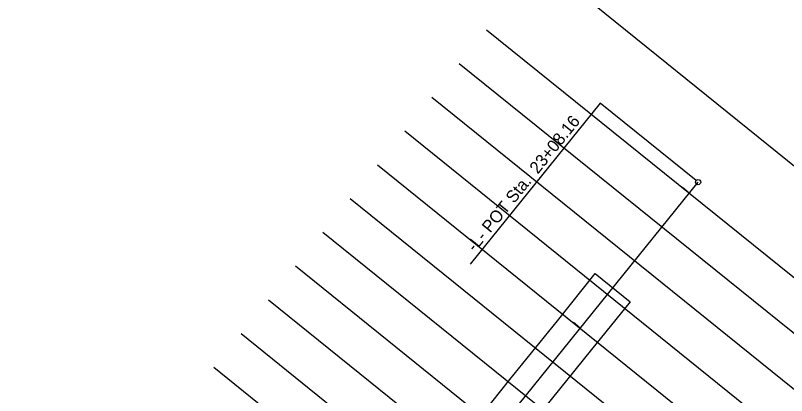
# Model space of a CAD drawing. Extents: x 2292992 to 2295123, y 892701 to 896230.
# Drawn here: x 2293899.6 to 2294343.7, y 893933 to 894152.2 of the extents above; entities that cross this region are included whole.
import ezdxf

# ---------------------------------------------------------------- set-up
doc = ezdxf.new("R2010")
doc.units = 0
for name, color, linetype in [('Prop EOT', 7, 'Continuous'), ('Prop Horizontal Alignment', 7, 'Continuous'), ('Prop Horizontal Alignment Station Label', 7, 'Continuous'), ('Prop Horizontal Alignment Tick Small', 7, 'Continuous'), ('Scratch_Level_3', 7, 'Continuous'), ('Scratch_Level_4', 7, 'Continuous'), ('Sheet Layout Plan Border', 7, 'Continuous')]:
    doc.layers.add(name, color=color, linetype=linetype)

msp = doc.modelspace()

# ---------------------------------------------------------------- linework, layer by layer
at = {"layer": 'Prop EOT'}
msp.add_line((2294233.51, 894003.43), (2294253.67, 893987.16), dxfattribs=at)
for points in [[(2294148.97, 893898.17), (2294158.28, 893909.61), (2294184.27, 893942.27), (2294211.74, 893976.09), (2294233.52, 894003.42)], [(2294168.97, 893882.04), (2294178.04, 893893.2), (2294203.54, 893924.89), (2294231.52, 893959.52), (2294253.69, 893987.15)]]:
    msp.add_lwpolyline(points, dxfattribs=at)
at = {"layer": 'Prop Horizontal Alignment'}
msp.add_line((2293686.78, 893305.28), (2294292.7, 894056.1), dxfattribs=at)
at = {"layer": 'Prop Horizontal Alignment Station Label'}
for p, q in [((2294236.26, 894101.65), (2294161.39, 894008.86)), ((2294291.53, 894057.05), (2294236.26, 894101.65))]:
    msp.add_line(p, q, dxfattribs=at)
msp.add_circle((2294292.7, 894056.1), 1.5, dxfattribs=at)
at = {"layer": 'Prop Horizontal Alignment Tick Small'}
for p, q in [((2294287.57, 894049.75), (2294283.68, 894052.89)), ((2294224.77, 893971.93), (2294220.88, 893975.07))]:
    msp.add_line(p, q, dxfattribs=at)
at = {"layer": 'Scratch_Level_3'}
msp.add_line((2293686.78, 893305.28), (2294292.7, 894056.1), dxfattribs=at)
at = {"layer": 'Scratch_Level_4'}
for p, q in [((2294170.84, 894143.95), (2294404.3, 893955.55)), ((2294155.14, 894124.5), (2294388.6, 893936.09)), ((2294139.44, 894105.04), (2294372.9, 893916.64)), ((2294123.74, 894085.59), (2294357.2, 893897.18)), ((2294108.04, 894066.13), (2294341.5, 893877.73)), ((2294092.34, 894046.68), (2294325.8, 893858.27)), ((2294076.64, 894027.22), (2294310.1, 893838.82)), ((2294060.94, 894007.77), (2294294.4, 893819.36)), ((2294045.24, 893988.31), (2294278.7, 893799.91)), ((2294029.54, 893968.86), (2294263, 893780.45)), ((2294013.84, 893949.4), (2294247.3, 893761))]:
    msp.add_line(p, q, dxfattribs=at)
at = {"layer": 'Sheet Layout Plan Border'}
msp.add_lwpolyline([(2293808.88, 892701.06), (2294688.51, 893790.22), (2293871.64, 894449.94), (2292992.02, 893360.79)], close=True, dxfattribs=at)

# ---------------------------------------------------------------- texts
at = {"layer": 'Prop Horizontal Alignment Station Label'}
msp.add_text('-L- POT Sta.  23+08.16', height=7, rotation=51.0961, dxfattribs=at).set_placement((2294164.18, 894015.47))

doc.saveas('drawing.dxf')
